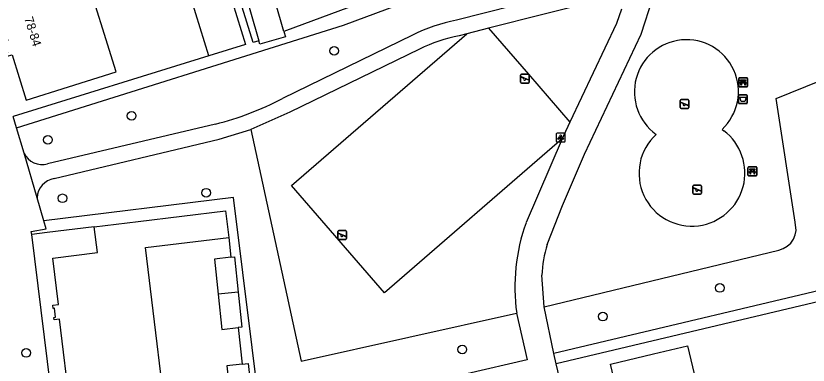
# Model space of a CAD drawing. Extents: x 158474 to 159560, y 388525 to 389605.
# Drawn here: x 159109 to 159198.5, y 388610.4 to 388649.8 of the extents above; entities that cross this region are included whole.
import ezdxf

# ---------------------------------------------------------------- set-up
doc = ezdxf.new("R2010")
doc.units = 0
for name, color, linetype in [('IMGEO_Afvalbak', 7, 'Continuous'), ('IMGEO_Bank', 7, 'Continuous'), ('IMGEO_Boom', 7, 'Continuous'), ('IMGEO_Groenvoorziening', 7, 'Continuous'), ('IMGEO_Lichtpunt', 7, 'Continuous'), ('IMGEO_Pand', 7, 'Continuous'), ('IMGEO_Pand_nummerreeks', 7, 'Continuous'), ('IMGEO_Speelvoorziening', 7, 'Continuous'), ('IMGEO_Voetpad_halfverhard', 7, 'Continuous'), ('IMGEO_Voetpad_open', 7, 'Continuous')]:
    doc.layers.add(name, color=color, linetype=linetype)

msp = doc.modelspace()

# ---------------------------------------------------------------- linework, layer by layer
at = {"layer": 'IMGEO_Afvalbak'}
for p, q in [((159190.636, 388640.023), (159190.636, 388640.823)), ((159190.636, 388640.823), (159190.636, 388640.023)), ((159190.736, 388640.923), (159191.526, 388640.923)), ((159191.526, 388640.923), (159190.736, 388640.923)), ((159191.626, 388640.823), (159191.626, 388640.023)), ((159191.626, 388640.023), (159191.626, 388640.823)), ((159191.526, 388639.923), (159190.736, 388639.923)), ((159190.736, 388639.923), (159191.526, 388639.923))]:
    msp.add_line(p, q, dxfattribs=at)
msp.add_lwpolyline([(159190.779, 388640.637), (159191.483, 388640.637), (159191.334, 388640.167), (159190.928, 388640.167), (159190.779, 388640.637)], dxfattribs=at)
for centre, start, end in [((159190.736, 388640.823), 90, 180), ((159190.736, 388640.823), 90, 180), ((159191.526, 388640.823), 0, 90), ((159191.526, 388640.823), 360, 90), ((159190.736, 388640.023), 180, 270), ((159190.736, 388640.023), 180, 270), ((159191.526, 388640.023), 270, 0), ((159191.526, 388640.023), 270, 0)]:
    msp.add_arc(centre, 0.1, start, end, dxfattribs=at)
at = {"layer": 'IMGEO_Bank'}
for p, q in [((159190.655, 388641.901), (159190.655, 388642.742)), ((159190.655, 388642.742), (159190.655, 388641.901)), ((159190.73, 388642.826), (159191.571, 388642.826)), ((159191.571, 388642.826), (159190.73, 388642.826)), ((159191.352, 388642.224), (159190.959, 388642.224)), ((159190.964, 388642.332), (159190.964, 388642.438)), ((159191.008, 388642.438), (159191.008, 388642.332)), ((159191.296, 388642.444), (159191.014, 388642.444)), ((159191.014, 388642.326), (159191.296, 388642.326)), ((159191.302, 388642.332), (159191.302, 388642.438)), ((159191.346, 388642.438), (159191.346, 388642.332)), ((159191.655, 388642.751), (159191.655, 388641.91)), ((159191.655, 388641.91), (159191.655, 388642.751)), ((159191.58, 388641.826), (159190.739, 388641.826)), ((159190.739, 388641.826), (159191.58, 388641.826)), ((159191.7, 388631.852), (159191.7, 388632.693)), ((159191.7, 388632.693), (159191.7, 388631.852)), ((159191.775, 388632.777), (159192.616, 388632.777)), ((159192.616, 388632.777), (159191.775, 388632.777)), ((159192.009, 388632.283), (159192.009, 388632.389)), ((159192.053, 388632.389), (159192.053, 388632.283)), ((159192.341, 388632.395), (159192.059, 388632.395)), ((159192.347, 388632.283), (159192.347, 388632.389)), ((159192.391, 388632.389), (159192.391, 388632.283)), ((159192.7, 388632.702), (159192.7, 388631.861)), ((159192.7, 388631.861), (159192.7, 388632.702)), ((159192.625, 388631.777), (159191.784, 388631.777)), ((159191.784, 388631.777), (159192.625, 388631.777)), ((159192.397, 388632.175), (159192.004, 388632.175)), ((159192.059, 388632.277), (159192.341, 388632.277))]:
    msp.add_line(p, q, dxfattribs=at)
for points in [[(159190.902, 388642.224), (159190.76, 388642.224), (159190.872, 388642.326), (159190.958, 388642.326)], [(159190.958, 388642.444), (159190.872, 388642.444), (159190.872, 388642.605), (159191.435, 388642.605), (159191.435, 388642.444), (159191.352, 388642.444)], [(159190.952, 388642.217), (159190.952, 388642.01), (159190.909, 388642.01), (159190.909, 388642.217)], [(159191.352, 388642.326), (159191.435, 388642.326), (159191.547, 388642.224), (159191.408, 388642.224)], [(159191.402, 388642.217), (159191.402, 388642.01), (159191.358, 388642.01), (159191.358, 388642.217)], [(159192.003, 388632.395), (159191.917, 388632.395), (159191.917, 388632.556), (159192.48, 388632.556), (159192.48, 388632.395), (159192.397, 388632.395)], [(159191.947, 388632.175), (159191.805, 388632.175), (159191.917, 388632.277), (159192.003, 388632.277)], [(159191.997, 388632.168), (159191.997, 388631.961), (159191.954, 388631.961), (159191.954, 388632.168)], [(159192.397, 388632.277), (159192.48, 388632.277), (159192.592, 388632.175), (159192.453, 388632.175)], [(159192.447, 388632.168), (159192.447, 388631.961), (159192.403, 388631.961), (159192.403, 388632.168)]]:
    msp.add_lwpolyline(points, dxfattribs=at)
for centre, radius, start, end in [((159190.733, 388642.748), 0.0779, 92.4484, 184.28452), ((159190.733, 388642.748), 0.0779, 92.4484, 184.28452), ((159190.902, 388642.217), 0.00671, 2.89567, 87.10433), ((159190.959, 388642.217), 0.00671, 92.89567, 177.10433), ((159190.957, 388642.437), 0.00671, 2.89567, 87.10433), ((159190.957, 388642.333), 0.00671, 272.89567, 357.10433), ((159191.014, 388642.437), 0.00671, 92.89567, 177.10433), ((159191.014, 388642.333), 0.00671, 182.89567, 267.10433), ((159191.296, 388642.437), 0.00671, 2.89567, 87.10433), ((159191.296, 388642.333), 0.00671, 272.89567, 357.10433), ((159191.353, 388642.437), 0.00671, 92.89567, 177.10433), ((159191.353, 388642.333), 0.00671, 182.89567, 267.10433), ((159191.351, 388642.217), 0.00671, 2.89567, 87.10433), ((159191.408, 388642.217), 0.00671, 92.89567, 177.10433), ((159191.577, 388642.748), 0.0779, 2.4484, 94.28452), ((159191.577, 388642.748), 0.0779, 2.4484, 94.28452), ((159190.733, 388641.904), 0.0779, 182.4484, 274.28452), ((159190.733, 388641.904), 0.0779, 182.4484, 274.28452), ((159191.577, 388641.904), 0.0779, 272.4484, 4.28452), ((159191.577, 388641.904), 0.0779, 272.4484, 4.28452), ((159191.778, 388632.699), 0.0779, 92.4484, 184.28452), ((159191.778, 388632.699), 0.0779, 92.4484, 184.28452), ((159192.002, 388632.388), 0.00671, 2.89567, 87.10433), ((159192.059, 388632.388), 0.00671, 92.89567, 177.10433), ((159192.341, 388632.388), 0.00671, 2.89567, 87.10433), ((159192.398, 388632.388), 0.00671, 92.89567, 177.10433), ((159192.622, 388632.699), 0.0779, 2.4484, 94.28452), ((159192.622, 388632.699), 0.0779, 2.4484, 94.28452), ((159191.778, 388631.855), 0.0779, 182.4484, 274.28452), ((159191.778, 388631.855), 0.0779, 182.4484, 274.28452), ((159191.947, 388632.168), 0.00671, 2.89567, 87.10433), ((159192.004, 388632.168), 0.00671, 92.89567, 177.10433), ((159192.002, 388632.284), 0.00671, 272.89567, 357.10433), ((159192.059, 388632.284), 0.00671, 182.89567, 267.10433), ((159192.341, 388632.284), 0.00671, 272.89567, 357.10433), ((159192.398, 388632.284), 0.00671, 182.89567, 267.10433), ((159192.396, 388632.168), 0.00671, 2.89567, 87.10433), ((159192.453, 388632.168), 0.00671, 92.89567, 177.10433), ((159192.622, 388631.855), 0.0779, 272.4484, 4.28452), ((159192.622, 388631.855), 0.0779, 272.4484, 4.28452)]:
    msp.add_arc(centre, radius, start, end, dxfattribs=at)
at = {"layer": 'IMGEO_Boom'}
for centre in [(159144.984, 388645.888), (159122.115, 388638.546), (159112.667, 388635.847), (159114.302, 388629.233), (159130.539, 388629.869), (159188.531, 388619.113), (159175.308, 388615.879), (159110.215, 388611.78), (159159.448, 388612.176)]:
    msp.add_circle(centre, 0.489, dxfattribs=at)
at = {"layer": 'IMGEO_Groenvoorziening'}
for points in [[(159170.704, 388635.942), (159150.658, 388618.573), (159140.181, 388630.666), (159159.958, 388647.801)], [(159162.422, 388648.428), (159166.92, 388643.248), (159166.913, 388643.242), (159171.591, 388637.842)], [(159168.696, 388616.985), (159195.192, 388623.391), (159195.688, 388623.56), (159196.139, 388623.829), (159196.524, 388624.186), (159196.826, 388624.615), (159197.032, 388625.097), (159197.134, 388625.611), (159197.042, 388626.545), (159194.87, 388640.508), (159199.815, 388642.509), (159199.819, 388643.8)], [(159135.584, 388636.984), (159141.242, 388610.851), (159165.584, 388616.269)], [(159188.768, 388637.007), (159188.959, 388636.868)]]:
    msp.add_lwpolyline(points, dxfattribs=at)
for centre, radius, start, end in [((159184.772, 388641.24), 5.897, 95.59947, 234.29556), ((159184.769, 388641.283), 5.854, 313.08221, 95.60984), ((159185.376, 388632.08), 5.98, 277.16455, 53.1916), ((159185.357, 388632.058), 5.96, 132.49864, 277.37068)]:
    msp.add_arc(centre, radius, start, end, dxfattribs=at)
at = {"layer": 'IMGEO_Lichtpunt'}
for p, q in [((159170.048, 388636.494), (159170.048, 388635.687)), ((159170.048, 388636.494), (159170.048, 388635.687)), ((159170.95, 388636.589), (159170.142, 388636.589)), ((159170.95, 388636.589), (159170.142, 388636.589)), ((159171.044, 388635.687), (159171.044, 388636.494)), ((159171.044, 388635.687), (159171.044, 388636.494)), ((159170.142, 388635.593), (159170.95, 388635.593)), ((159170.142, 388635.593), (159170.95, 388635.593))]:
    msp.add_line(p, q, dxfattribs=at)
for points in [[(159170.422, 388636.158), (159170.461, 388636.13), (159170.273, 388635.868), (159170.235, 388635.895), (159170.422, 388636.158)], [(159170.524, 388636.11), (159170.571, 388636.11), (159170.571, 388635.788), (159170.524, 388635.788), (159170.524, 388636.11)], [(159170.634, 388636.13), (159170.672, 388636.157), (159170.859, 388635.895), (159170.82, 388635.867), (159170.634, 388636.13)]]:
    msp.add_lwpolyline(points, dxfattribs=at)
msp.add_circle((159170.547, 388636.292), 0.0994, dxfattribs=at)
for centre, start, end in [((159170.142, 388636.494), 90, 180), ((159170.142, 388636.494), 90, 180), ((159170.95, 388636.494), 0, 90), ((159170.95, 388636.494), 0, 90), ((159170.142, 388635.687), 180, 270), ((159170.142, 388635.687), 180, 270), ((159170.95, 388635.687), 270, 0), ((159170.95, 388635.687), 270, 360)]:
    msp.add_arc(centre, 0.0946, start, end, dxfattribs=at)
at = {"layer": 'IMGEO_Pand'}
for points in [[(159106.567, 388652.018), (159108.121, 388647.066), (159107.527, 388646.88), (159107.632, 388646.547), (159107.812, 388646.604), (159108.113, 388645.644), (159107.959, 388645.596), (159108.064, 388645.263), (159108.614, 388645.435), (159110.216, 388640.33), (159114.987, 388641.827), (159120.372, 388643.517), (159116.71, 388655.198)], [(159139.306, 388648.077), (159137.479, 388654.38)], [(159134.649, 388653.326), (159136.476, 388647.027)], [(159133.018, 388652.94), (159134.984, 388646.594), (159130.843, 388645.311)], [(159130.843, 388645.311), (159128.877, 388651.657)], [(159139.306, 388648.077), (159139.481, 388647.475), (159136.589, 388646.637), (159136.476, 388647.027)], [(159117.888, 388626.023), (159122.852, 388626.627), (159132.715, 388627.827), (159133.082, 388624.813)], [(159115.211, 388605.364), (159113.966, 388615.594), (159113.355, 388615.52), (159113.324, 388615.781), (159113.532, 388615.807), (159113.408, 388616.824), (159113.246, 388616.804), (159113.202, 388617.169), (159113.863, 388617.249), (159113.226, 388622.491), (159118.243, 388623.101), (159117.888, 388626.023)], [(159126.975, 388575.508), (159129.482, 388575.813), (159123.66, 388623.667), (159133.082, 388624.813)], [(159133.316, 388622.576), (159131.457, 388622.381), (159131.874, 388618.412)], [(159133.316, 388622.576), (159133.72, 388622.618), (159134.137, 388618.65)], [(159134.137, 388618.65), (159131.874, 388618.412)], [(159131.874, 388618.412), (159132.29, 388614.444), (159134.156, 388614.64)], [(159134.137, 388618.65), (159134.554, 388614.682), (159134.156, 388614.64)], [(159177.442, 388605.147), (159176.161, 388610.525), (159181.025, 388611.683), (159184.861, 388612.597), (159186.142, 388607.219)], [(159134.589, 388610.523), (159132.867, 388610.339), (159133.048, 388608.638), (159131.587, 388608.481), (159131.795, 388606.528), (159133.291, 388606.688)], [(159134.589, 388610.523), (159135.279, 388610.597), (159135.67, 388606.942)]]:
    msp.add_lwpolyline(points, dxfattribs=at)
at = {"layer": 'IMGEO_Speelvoorziening'}
for p, q in [((159166.023, 388642.342), (159166.023, 388643.142)), ((159166.023, 388643.142), (159166.023, 388642.342)), ((159166.123, 388643.242), (159166.913, 388643.242)), ((159166.913, 388643.242), (159166.123, 388643.242)), ((159167.013, 388643.142), (159167.013, 388642.342)), ((159167.013, 388642.342), (159167.013, 388643.142)), ((159166.406, 388642.77), (159166.067, 388642.907)), ((159166.092, 388642.967), (159166.968, 388642.614)), ((159166.913, 388642.242), (159166.123, 388642.242)), ((159166.123, 388642.242), (159166.913, 388642.242)), ((159166.944, 388642.554), (159166.604, 388642.691)), ((159184.042, 388639.477), (159184.042, 388640.277)), ((159184.042, 388640.277), (159184.042, 388639.477)), ((159184.425, 388639.905), (159184.086, 388640.042)), ((159184.111, 388640.102), (159184.987, 388639.749)), ((159184.142, 388640.377), (159184.932, 388640.377)), ((159184.932, 388640.377), (159184.142, 388640.377)), ((159184.963, 388639.689), (159184.623, 388639.826)), ((159185.032, 388640.277), (159185.032, 388639.477)), ((159185.032, 388639.477), (159185.032, 388640.277)), ((159184.932, 388639.377), (159184.142, 388639.377)), ((159184.142, 388639.377), (159184.932, 388639.377)), ((159185.468, 388629.817), (159185.468, 388630.617)), ((159185.468, 388630.617), (159185.468, 388629.817)), ((159185.568, 388630.717), (159186.358, 388630.717)), ((159186.358, 388630.717), (159185.568, 388630.717)), ((159186.458, 388630.617), (159186.458, 388629.817)), ((159186.458, 388629.817), (159186.458, 388630.617)), ((159185.851, 388630.245), (159185.512, 388630.382)), ((159185.537, 388630.442), (159186.413, 388630.089)), ((159186.358, 388629.717), (159185.568, 388629.717)), ((159185.568, 388629.717), (159186.358, 388629.717)), ((159186.389, 388630.029), (159186.049, 388630.166)), ((159145.39, 388624.69), (159145.39, 388625.49)), ((159145.39, 388625.49), (159145.39, 388624.69)), ((159145.773, 388625.118), (159145.434, 388625.255)), ((159145.459, 388625.315), (159146.335, 388624.962)), ((159145.49, 388625.59), (159146.28, 388625.59)), ((159146.28, 388625.59), (159145.49, 388625.59)), ((159146.38, 388625.49), (159146.38, 388624.69)), ((159146.38, 388624.69), (159146.38, 388625.49)), ((159146.28, 388624.59), (159145.49, 388624.59)), ((159145.49, 388624.59), (159146.28, 388624.59)), ((159146.311, 388624.902), (159145.971, 388625.039))]:
    msp.add_line(p, q, dxfattribs=at)
for centre, radius, start, end in [((159166.123, 388643.142), 0.1, 90, 180), ((159166.123, 388643.142), 0.1, 90, 180), ((159166.913, 388643.142), 0.1, 0, 90), ((159166.913, 388643.142), 0.1, 360, 90), ((159166.123, 388642.342), 0.1, 180, 270), ((159166.123, 388642.342), 0.1, 180, 270), ((159166.08, 388642.937), 0.0327, 68.07798, 248.07798), ((159166.485, 388642.68), 0.12, 130.99278, 5.16318), ((159166.913, 388642.342), 0.1, 270, 0), ((159166.913, 388642.342), 0.1, 270, 0), ((159166.956, 388642.584), 0.0327, 248.07798, 68.07798), ((159184.142, 388640.277), 0.1, 90, 180), ((159184.142, 388640.277), 0.1, 90, 180), ((159184.099, 388640.072), 0.0327, 68.07798, 248.07798), ((159184.504, 388639.815), 0.12, 130.99278, 5.16318), ((159184.932, 388640.277), 0.1, 0, 90), ((159184.932, 388640.277), 0.1, 360, 90), ((159184.975, 388639.719), 0.0327, 248.07798, 68.07798), ((159184.142, 388639.477), 0.1, 180, 270), ((159184.142, 388639.477), 0.1, 180, 270), ((159184.932, 388639.477), 0.1, 270, 0), ((159184.932, 388639.477), 0.1, 270, 0), ((159185.568, 388630.617), 0.1, 90, 180), ((159185.568, 388630.617), 0.1, 90, 180), ((159186.358, 388630.617), 0.1, 0, 90), ((159186.358, 388630.617), 0.1, 360, 90), ((159185.568, 388629.817), 0.1, 180, 270), ((159185.568, 388629.817), 0.1, 180, 270), ((159185.525, 388630.412), 0.0327, 68.07798, 248.07798), ((159185.93, 388630.155), 0.12, 130.99278, 5.16318), ((159186.358, 388629.817), 0.1, 270, 0), ((159186.358, 388629.817), 0.1, 270, 0), ((159186.401, 388630.059), 0.0327, 248.07798, 68.07798), ((159145.49, 388625.49), 0.1, 90, 180), ((159145.49, 388625.49), 0.1, 90, 180), ((159145.447, 388625.285), 0.0327, 68.07798, 248.07798), ((159146.28, 388625.49), 0.1, 0, 90), ((159146.28, 388625.49), 0.1, 360, 90), ((159145.49, 388624.69), 0.1, 180, 270), ((159145.49, 388624.69), 0.1, 180, 270), ((159145.852, 388625.028), 0.12, 130.99278, 5.16318), ((159146.28, 388624.69), 0.1, 270, 0), ((159146.28, 388624.69), 0.1, 270, 0), ((159146.323, 388624.932), 0.0327, 248.07798, 68.07798)]:
    msp.add_arc(centre, radius, start, end, dxfattribs=at)
at = {"layer": 'IMGEO_Voetpad_halfverhard'}
for points in [[(159178.144, 388654.261), (159158.774, 388649.33)], [(159174.96, 388651.617), (159162.422, 388648.428)], [(159153.814, 388647.658), (159139.141, 388640.512)], [(159159.958, 388647.801), (159159.105, 388647.584)], [(159162.422, 388648.428), (159159.958, 388647.801)], [(159154.607, 388646.068), (159139.977, 388638.944), (159135.584, 388636.984)], [(159131.576, 388637.622), (159112.627, 388633.125)], [(159113.367, 388631.474), (159131.998, 388635.896), (159135.584, 388636.984)]]:
    msp.add_lwpolyline(points, dxfattribs=at)
for centre, radius, start, end in [((159162.324, 388630.607), 19.056, 100.73505, 116.52254), ((159162.332, 388630.58), 17.308, 100.74438, 116.50723), ((159123.872, 388669.134), 32.44, 283.73779, 298.07817), ((159112.006, 388635.307), 2.269, 205.67826, 285.89127), ((159113.767, 388629.175), 2.333, 99.87193, 177.01146)]:
    msp.add_arc(centre, radius, start, end, dxfattribs=at)
at = {"layer": 'IMGEO_Voetpad_open'}
for points in [[(159136.476, 388647.027), (159135.832, 388646.84), (159127.015, 388675.098), (159157.256, 388686.318)], [(159168.969, 388659.082), (159139.306, 388648.077)], [(159109.117, 388637.198), (159146.049, 388648.789), (159169.54, 388657.542)], [(159169.045, 388624.022), (159170.745, 388628.434), (159173.233, 388634.233), (159179.641, 388647.749), (159180.948, 388651.854)], [(159177.412, 388650.576), (159176.863, 388648.953), (159171.591, 388637.842)], [(159130.843, 388645.311), (159108.722, 388638.457)], [(159200.073, 388643.862), (159205.64, 388620.22), (159169.776, 388611.735)], [(159109.117, 388637.198), (159108.722, 388638.457)], [(159171.591, 388637.842), (159170.859, 388636.301), (159170.704, 388635.942)], [(159109.961, 388634.324), (159109.117, 388637.198)], [(159170.704, 388635.942), (159166.638, 388626.486)], [(159111.437, 388629.297), (159109.961, 388634.324)], [(159112.201, 388626.693), (159111.437, 388629.297)], [(159159.973, 388609.415), (159136.768, 388603.925), (159133.628, 388629.312), (159112.201, 388626.693)], [(159110.83, 388625.149), (159110.787, 388625.495), (159112.466, 388625.791), (159112.201, 388626.693)], [(159117.888, 388626.023), (159112.591, 388625.367), (159110.83, 388625.149)], [(159118.785, 388560.939), (159118.272, 388565.079), (159110.83, 388625.149)], [(159133.082, 388624.813), (159133.316, 388622.576)], [(159168.696, 388616.985), (159168.435, 388620.55)], [(159202.693, 388615.085), (159201.971, 388618.129), (159170.055, 388610.56)], [(159165.584, 388616.269), (159166.772, 388611.015), (159159.973, 388609.415)], [(159169.776, 388611.735), (159168.696, 388616.985)], [(159134.156, 388614.64), (159134.589, 388610.523)], [(159170.055, 388610.56), (159169.776, 388611.735)], [(159177.94, 388581.388), (159177.021, 388581.185), (159170.055, 388610.56)]]:
    msp.add_lwpolyline(points, dxfattribs=at)
for centre, radius, start, end in [((159187.09, 388619.213), 21.706, 160.42443, 187.79582), ((159179.912, 388620.323), 11.479, 161.20252, 178.86814)]:
    msp.add_arc(centre, radius, start, end, dxfattribs=at)

# ---------------------------------------------------------------- texts
at = {"layer": 'IMGEO_Pand_nummerreeks'}
msp.add_text('78-84', height=1, rotation=287.33839, dxfattribs=at).set_placement((159109.979, 388649.546))

doc.saveas('drawing.dxf')
